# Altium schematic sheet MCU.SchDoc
size 177 x 114 mm; SheetNumber: 1; SheetTotal: 1
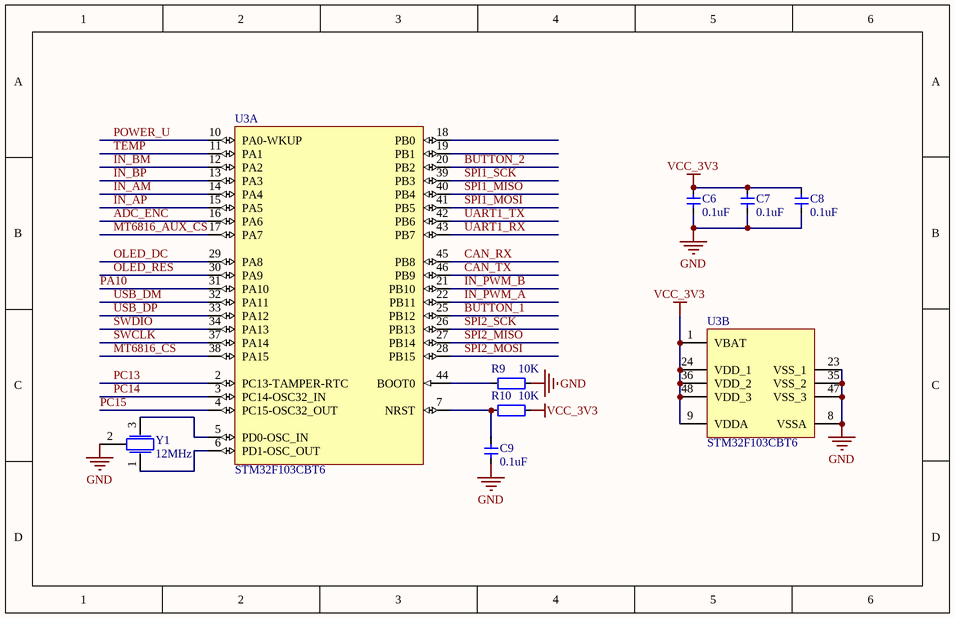
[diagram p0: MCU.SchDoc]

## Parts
C6  0.1uF  [CAP_0402]
C7  0.1uF  [CAP_0402]
C8  0.1uF  [CAP_0402]
C9  0.1uF  [CAP_0402]
R9  10K  [RES_0402]
R10  10K  [RES_0402]
U3  STM32F103CBT6  [LQFP-48]  (parts A,B of 2)
Y1  12MHz  [晶振-3P]

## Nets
GND: C6.1 C7.1 C8.1 C9.1 R9.2 U3.8(VSSA) U3.23(VSS_1) U3.35(VSS_2) U3.47(VSS_3) Y1.2
VCC_3V3: C6.2 C7.2 C8.2 R10.2 U3.1(VBAT) U3.9(VDDA) U3.24(VDD_1) U3.36(VDD_2) U3.48(VDD_3)
ADC_ENC: U3.16(PA6)
BUTTON_1: U3.25(PB12)
BUTTON_2: U3.20(PB2)
CAN_RX: U3.45(PB8)
CAN_TX: U3.46(PB9)
IN_AM: U3.14(PA4)
IN_AP: U3.15(PA5)
IN_BM: U3.12(PA2)
IN_BP: U3.13(PA3)
IN_PWM_A: U3.22(PB11)
IN_PWM_B: U3.21(PB10)
MT6816_AUX_CS: U3.17(PA7)
MT6816_CS: U3.38(PA15)
OLED_DC: U3.29(PA8)
OLED_RES: U3.30(PA9)
PA10: U3.31(PA10)
PC13: U3.2(PC13-TAMPER-RTC)
PC14: U3.3(PC14-OSC32_IN)
PC15: U3.4(PC15-OSC32_OUT)
POWER_U: U3.10(PA0-WKUP)
SPI1_MISO: U3.40(PB4)
SPI1_MOSI: U3.41(PB5)
SPI1_SCK: U3.39(PB3)
SPI2_MISO: U3.27(PB14)
SPI2_MOSI: U3.28(PB15)
SPI2_SCK: U3.26(PB13)
SWCLK: U3.37(PA14)
SWDIO: U3.34(PA13)
TEMP: U3.11(PA1)
UART1_RX: U3.43(PB7)
UART1_TX: U3.42(PB6)
USB_DM: U3.32(PA11)
USB_DP: U3.33(PA12)
NetC9_2: C9.2 R10.1 U3.7(NRST)
NetR9_1: R9.1 U3.44(BOOT0)
NetU3_5: U3.5(PD0-OSC_IN) Y1.3
NetU3_6: U3.6(PD1-OSC_OUT) Y1.1

Not connected (* = marked no-connect by the designer): U3 18(PB0) 19(PB1)

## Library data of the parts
C6-C9 = 电容-0402: Capacitor; Value: 0.1u
R9 R10 = 电阻-0402: Resistor; Value: 22R
U3 = STM32F103CBT6: ARM Cortex-M3 32-bit MCU, 128 KB Flash, 20 KB Internal RAM, 37 I/Os, 48-pin LQFP, -40 to 85 degC, Tray; A/D Converter: 2x12-bit (10 Channel); FLASH Size (Prog) (kB): 128; I/Os (High Current): 37; Internal RAM Size (kB): 20; Operating Frequency(F) (Processor speed) (MHz): 72; Supply Voltage(Vcc) min (V): 2
Y1 = 晶振-3Pin: 村田贴片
